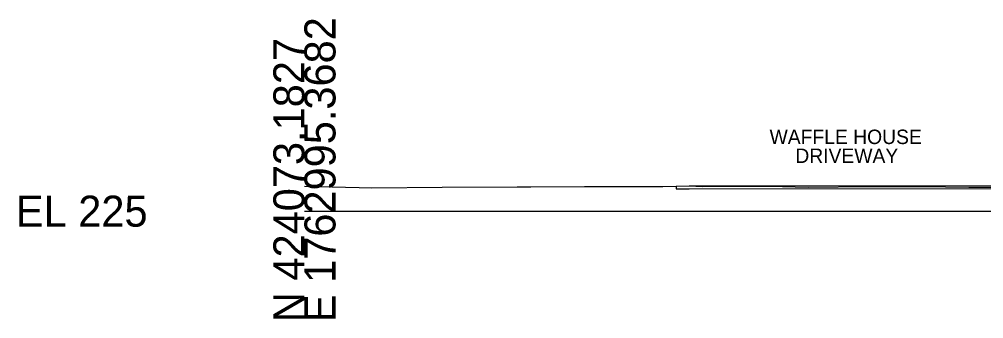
# Model space of a CAD drawing. Extents: x -26 to 3203, y -11010 to 4024.
# Drawn here: x 974.3 to 1061.2, y 2990.3 to 3017.3 of the extents above; entities that cross this region are included whole.
import ezdxf

# ---------------------------------------------------------------- set-up
doc = ezdxf.new("R2010")
doc.units = 0
for name, color, linetype in [('Default', 7, 'Continuous'), ('Exist Cross Section Cell', 7, 'Continuous'), ('Exist XS Ground Line', 7, 'Continuous'), ('Prop CMT Pvmt Course 1', 7, 'Continuous'), ('Prop CMT Pvmt Surface', 7, 'Continuous'), ('Prop CMT Shear Line Text', 7, 'Continuous')]:
    doc.layers.add(name, color=color, linetype=linetype)

msp = doc.modelspace()

# ---------------------------------------------------------------- linework, layer by layer
at = {"layer": 'Exist Cross Section Cell'}
msp.add_line((1000, 3000), (1100, 3000), dxfattribs=at)
at = {"layer": 'Exist XS Ground Line'}
msp.add_lwpolyline([(1000, 3002.248), (1004.924, 3002.122), (1006.07, 3002.118), (1012.426, 3002.159), (1019.176, 3002.207), (1020.394, 3002.199), (1025.245, 3002.214), (1032.282, 3002.233), (1034.661, 3002.272), (1035.865, 3002.213), (1041.269, 3002.262), (1041.908, 3002.258), (1045.389, 3002.168), (1050.828, 3002.212), (1052.663, 3002.233), (1057.765, 3002.187), (1059.876, 3002.167), (1060.3, 3002.171), (1061.039, 3002.162), (1061.201, 3002.164), (1062.098, 3002.17)], dxfattribs=at)
msp.add_lwpolyline([(1000, 3002.248), (1004.924, 3002.122), (1006.07, 3002.118), (1012.426, 3002.159), (1019.176, 3002.207), (1020.394, 3002.199), (1025.245, 3002.214), (1032.282, 3002.233), (1034.661, 3002.272), (1035.865, 3002.213), (1041.269, 3002.262), (1041.908, 3002.258), (1045.389, 3002.168), (1050.828, 3002.212), (1052.663, 3002.233), (1057.765, 3002.187), (1059.876, 3002.167), (1060.3, 3002.171), (1061.039, 3002.162), (1061.201, 3002.164), (1062.098, 3002.17)], dxfattribs=at)
msp.add_lwpolyline([(1000, 3002.248), (1004.924, 3002.122), (1006.07, 3002.118), (1012.426, 3002.159), (1019.176, 3002.207), (1020.394, 3002.199), (1025.245, 3002.214), (1032.282, 3002.233), (1034.661, 3002.272), (1035.865, 3002.213), (1041.269, 3002.262), (1041.908, 3002.258), (1045.389, 3002.168), (1050.828, 3002.212), (1052.663, 3002.233), (1057.765, 3002.187), (1059.876, 3002.167), (1060.3, 3002.171), (1061.039, 3002.162), (1061.201, 3002.164), (1062.098, 3002.17)], dxfattribs=at)
msp.add_lwpolyline([(1000, 3002.248), (1004.924, 3002.122), (1006.07, 3002.118), (1012.426, 3002.159), (1019.176, 3002.207), (1020.394, 3002.199), (1025.245, 3002.214), (1032.282, 3002.233), (1034.661, 3002.272), (1035.865, 3002.213), (1041.269, 3002.262), (1041.908, 3002.258), (1045.389, 3002.168), (1050.828, 3002.212), (1052.663, 3002.233), (1057.765, 3002.187), (1059.876, 3002.167), (1060.3, 3002.171), (1061.039, 3002.162), (1061.201, 3002.164), (1062.098, 3002.17)], dxfattribs=at)
msp.add_lwpolyline([(1000, 3002.248), (1004.924, 3002.122), (1006.07, 3002.118), (1012.426, 3002.159), (1019.176, 3002.207), (1020.394, 3002.199), (1025.245, 3002.214), (1032.282, 3002.233), (1034.661, 3002.272), (1035.865, 3002.213), (1041.269, 3002.262), (1041.908, 3002.258), (1045.389, 3002.168), (1050.828, 3002.212), (1052.663, 3002.233), (1057.765, 3002.187), (1059.876, 3002.167), (1060.3, 3002.171), (1061.039, 3002.162), (1061.201, 3002.164), (1062.098, 3002.17)], dxfattribs=at)
at = {"layer": 'Prop CMT Pvmt Course 1'}
for p, q in [((1033.504, 3002.253), (1033.504, 3002.003)), ((1033.508, 3002.003), (1034.663, 3002.022)), ((1034.663, 3002.022), (1063.65, 3002.056))]:
    msp.add_line(p, q, dxfattribs=at)
at = {"layer": 'Prop CMT Pvmt Surface'}
for p, q in [((1033.504, 3002.253), (1034.661, 3002.272)), ((1034.661, 3002.272), (1063.65, 3002.306))]:
    msp.add_line(p, q, dxfattribs=at)

# ---------------------------------------------------------------- texts
at = {"layer": 'Default'}
msp.add_text('-', height=0.0001, dxfattribs=at).set_placement((1000, 3000))
at = {"layer": 'Exist Cross Section Cell'}
for s, p in [('E 1762995.3682', (1002.8, 2990)), ('N 424073.1827', (1000, 2990))]:
    msp.add_text(s, height=2.8, rotation=90, dxfattribs=at).set_placement(p)
msp.add_text('EL 225', height=2.8, dxfattribs=at).set_placement((974, 2998.6))
at = {"layer": 'Prop CMT Shear Line Text'}
for s, p in [('WAFFLE HOUSE', (1041.913, 3006.05)), ('DRIVEWAY', (1044.234, 3004.346))]:
    msp.add_text(s, height=1.3, rotation=360, dxfattribs=at).set_placement(p)

doc.saveas('drawing.dxf')
